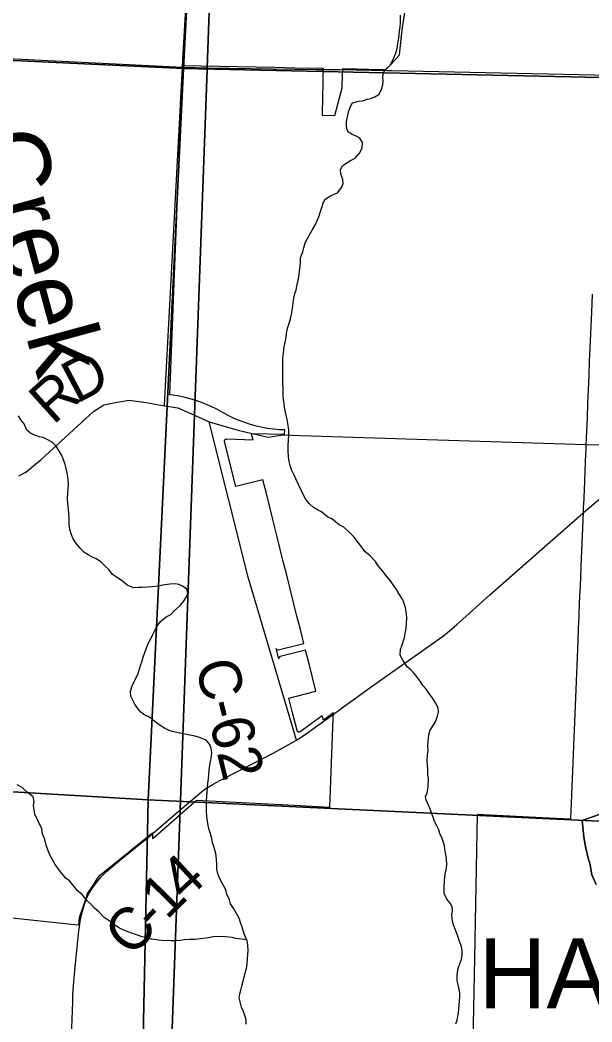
# Model space of a CAD drawing. Extents: x -7.5 to 26.5, y 3.5 to 25.5.
# Drawn here: x -2.42 to -1.65, y 21.822 to 23.173 of the extents above; entities that cross this region are included whole.
import ezdxf

# ---------------------------------------------------------------- set-up
doc = ezdxf.new("R2010")
doc.units = 0
for name, color, linetype in [('GM_X_Corporation', 7, 'Continuous'), ('GM_X_Corporation_Text', 7, 'Continuous'), ('GM_X_County_Road', 7, 'Continuous'), ('GM_X_County_Road_Text', 7, 'Continuous'), ('GM_X_Minor_River', 7, 'Continuous'), ('GM_X_Minor_River_Text', 7, 'Continuous')]:
    doc.layers.add(name, color=color, linetype=linetype)

msp = doc.modelspace()

# ---------------------------------------------------------------- linework, layer by layer
at = {"layer": 'GM_X_Corporation'}
for points in [[(-3.3166, 19.1895), (-2.696, 19.1768), (-2.693, 19.1768), (-2.3401, 19.1651), (-2.3128, 19.1642), (-2.2728, 20.2496), (-2.265, 20.4395), (-2.2643, 20.4572), (-2.2393, 21.1622), (-2.2218, 21.6412), (-2.2048, 22.1084), (-2.1854, 22.6407), (-2.1684, 23.1064), (-2.1683, 23.1094), (-2.1213, 24.4), (-5.1194, 24.4)], [(-2.1213, 24.4), (-2.1683, 23.1094), (-2.1684, 23.1064), (-2.1854, 22.6407), (-2.2048, 22.1084), (-2.2218, 21.6412), (-2.2393, 21.1622), (-1.7013, 21.1435), (-0.6673, 21.1123), (-0.2751, 21.1005), (-0.1918, 21.0972), (-0.1864, 21.0971), (-0.1806, 21.0967), (-0.0857, 21.093), (-0.0438, 21.0913), (0.0729, 21.0875), (0.2211, 21.0828)], [(-2.4486, 21.964), (-2.3846, 21.9575), (-2.3469, 21.9535), (-2.3413, 21.9531), (-2.3403, 21.9627), (-2.3345, 21.9798), (-2.3315, 21.9885), (-2.3293, 21.9951), (-2.3251, 22.0015), (-2.3137, 22.0189), (-2.2417, 22.0771), (-2.2419, 22.0696), (-2.238, 22.0727), (-2.1826, 22.1209), (-2.0595, 22.1147), (-2.0029, 22.1118), (-1.9982, 22.2314), (-1.9979, 22.2387), (-2.0116, 22.2289), (-2.0131, 22.2348), (-2.0427, 22.2134), (-2.0431, 22.2132), (-2.0435, 22.213), (-2.044, 22.2129), (-2.0444, 22.2129), (-2.0449, 22.213), (-2.0453, 22.2131), (-2.0458, 22.2133), (-2.0461, 22.2135), (-2.0465, 22.2138), (-2.0468, 22.2142), (-2.047, 22.2146), (-2.0471, 22.215), (-2.0536, 22.2405), (-2.0583, 22.2589), (-2.0215, 22.2682), (-2.0262, 22.2865), (-2.0309, 22.3049), (-2.0356, 22.3234), (-2.07, 22.3147), (-2.0704, 22.3146), (-2.0707, 22.3144), (-2.071, 22.3142), (-2.0712, 22.3139), (-2.0715, 22.3136), (-2.0716, 22.3133), (-2.0717, 22.3129), (-2.0718, 22.3125), (-2.0718, 22.3122), (-2.0717, 22.3118), (-2.0752, 22.3256), (-2.0751, 22.3252), (-2.0749, 22.3249), (-2.0747, 22.3246), (-2.0744, 22.3243), (-2.0741, 22.3241), (-2.0738, 22.324), (-2.0734, 22.3239), (-2.0731, 22.3238), (-2.0727, 22.3238), (-2.0723, 22.3239), (-2.0379, 22.3326), (-2.0426, 22.3511), (-2.0473, 22.3695), (-2.0519, 22.3878), (-2.0564, 22.4062), (-2.061, 22.4246), (-2.0656, 22.443), (-2.0701, 22.4614), (-2.0747, 22.4798), (-2.0793, 22.4981), (-2.0838, 22.5165), (-2.0884, 22.5349), (-2.093, 22.5533), (-2.1297, 22.5442), (-2.1448, 22.6048), (-2.1448, 22.6051), (-2.1448, 22.6055), (-2.1448, 22.606), (-2.1447, 22.6064), (-2.1445, 22.6068), (-2.1442, 22.6072), (-2.1439, 22.6075), (-2.1436, 22.6078), (-2.1432, 22.608), (-2.1428, 22.6082), (-2.1424, 22.6083), (-2.1419, 22.6083), (-2.1064, 22.6073), (-2.1066, 22.6083), (-2.1083, 22.6149), (-2.1085, 22.6159), (-2.0638, 22.6148), (-2.0636, 22.6201), (-2.0636, 22.6204), (-2.0712, 22.6207), (-2.0788, 22.6214), (-2.0863, 22.6224), (-2.0938, 22.6238), (-2.1017, 22.6256), (-2.1096, 22.6278), (-2.1174, 22.6303), (-2.1251, 22.6332), (-2.1326, 22.6365), (-2.14, 22.6401), (-2.1471, 22.6441), (-2.155, 22.6484), (-2.163, 22.6523), (-2.1712, 22.6558), (-2.1795, 22.659), (-2.188, 22.6617), (-2.1966, 22.664), (-2.2054, 22.666), (-2.2142, 22.6674), (-2.2144, 22.6675), (-2.2183, 22.668), (-2.2121, 22.8305), (-2.2069, 22.9655), (-2.2042, 23.0366), (-2.2034, 23.0548), (-2.2012, 23.1121), (-2.0776, 23.1096), (-2.049, 23.109), (-2.0119, 23.1083), (-2.012, 23.1026), (-2.0121, 23.1007), (-2.0122, 23.0926), (-2.0124, 23.0828), (-2.0126, 23.0743), (-2.0128, 23.0637), (-2.013, 23.0531), (-2.0132, 23.0451), (-1.9962, 23.0447), (-1.9861, 23.0818), (-1.9856, 23.1002), (-1.9853, 23.1078), (-1.9671, 23.1074), (-1.934, 23.1067), (-1.9274, 23.1066), (-1.9204, 23.114), (-1.9089, 23.1263), (-1.9054, 23.1601), (-1.8992, 23.201)], [(-1.6494, 22.8036), (-1.6499, 22.7904), (-1.6508, 22.7695), (-1.6516, 22.7506), (-1.6523, 22.7317), (-1.6531, 22.7127), (-1.6539, 22.6938), (-1.6547, 22.6749), (-1.6555, 22.656), (-1.6562, 22.637), (-1.657, 22.6181), (-1.6574, 22.6094), (-1.6574, 22.6082), (-1.6577, 22.6019), (-1.6579, 22.5966), (-1.658, 22.5943), (-1.6583, 22.5867), (-1.6587, 22.578), (-1.6598, 22.551), (-1.6602, 22.5399), (-1.6611, 22.5196), (-1.6612, 22.5166), (-1.6615, 22.5092), (-1.6615, 22.5077), (-1.6618, 22.5009), (-1.6619, 22.4987), (-1.664, 22.4471), (-1.6645, 22.4368), (-1.6651, 22.4218), (-1.6656, 22.4095), (-1.6661, 22.3972), (-1.6666, 22.3849), (-1.6671, 22.3726), (-1.6673, 22.3688), (-1.6679, 22.3535), (-1.6686, 22.3353), (-1.6695, 22.314), (-1.6785, 22.0956), (-1.7075, 22.097), (-1.8042, 22.1019), (-1.8079, 21.9086), (-1.8101, 21.7954)]]:
    msp.add_lwpolyline(points, dxfattribs=at)
for points in [[(-3.1693, 24.148), (-2.147, 24.1207), (-2.1999, 23.1078), (-3.2023, 23.155), (-3.2132, 23.1565)], [(-2.147, 24.1207), (-0.8988, 24.09), (-0.9286, 23.0807), (-2.1999, 23.1078)], [(-3.2023, 23.155), (-2.1999, 23.1078), (-2.2479, 22.1217), (-3.2367, 22.18)], [(-2.1999, 23.1078), (-0.9286, 23.0807), (-0.9291, 23.0451), (-0.9461, 22.0601), (-2.2479, 22.1217)], [(-3.2367, 22.18), (-2.2479, 22.1217), (-2.268, 21.1618), (-3.2602, 21.1789)], [(-2.2479, 22.1217), (-0.9461, 22.0601), (-0.9782, 21.2998), (-1.0267, 21.301), (-1.0307, 21.1237), (-1.2798, 21.1309), (-2.268, 21.1618)]]:
    msp.add_lwpolyline(points, close=True, dxfattribs=at)
at = {"layer": 'GM_X_County_Road'}
msp.add_line((-2.2258, 22.6528), (-2.2253, 22.663), dxfattribs=at)
for points in [[(-2.2008, 23.1201), (-2.1874, 23.3495), (-2.1808, 23.4761), (-2.1743, 23.6146), (-2.1737, 23.6247)], [(-2.6198, 23.1291), (-2.6056, 23.1283), (-2.5689, 23.1263), (-2.4645, 23.1228), (-2.2014, 23.11)], [(-2.2253, 22.663), (-2.2249, 22.6711), (-2.2014, 23.11), (-2.2008, 23.1201)], [(-2.2014, 23.11), (-2.1681, 23.1089), (-2.0209, 23.1066), (-2.0097, 23.1066)], [(-2.0097, 23.1066), (-1.9943, 23.1066), (-1.9893, 23.1065)], [(-1.9893, 23.1065), (-1.9258, 23.1052), (-1.9187, 23.1051)], [(-1.9187, 23.1051), (-1.6459, 23.0994), (-1.6361, 23.0992)], [(-1.6568, 22.6007), (-1.6367, 22.6004), (-1.5995, 22.5991), (-1.5848, 22.5989), (-1.5737, 22.6001), (-1.5662, 22.6016), (-1.5536, 22.6067), (-1.5321, 22.6175), (-1.5067, 22.63), (-1.4479, 22.6575), (-1.3991, 22.6922), (-1.3695, 22.7151), (-1.1787, 22.8635), (-0.9469, 23.0417)], [(-2.4221, 22.5586), (-2.4125, 22.5636), (-2.3918, 22.5808), (-2.3213, 22.6453), (-2.3074, 22.6544), (-2.2921, 22.6577), (-2.2734, 22.6605), (-2.2503, 22.6574), (-2.2258, 22.6528)], [(-2.2258, 22.6528), (-2.2077, 22.6503), (-2.1852, 22.6402), (-2.1653, 22.6313), (-2.1251, 22.6197)], [(-2.0477, 22.2022), (-2.1131, 22.4221), (-2.1653, 22.6313)], [(-2.1251, 22.6197), (-2.121, 22.6186), (-2.086, 22.6106), (-2.0745, 22.6125)], [(-2.0745, 22.6125), (-2.0661, 22.6139), (-2.0426, 22.6128), (-1.6579, 22.6007), (-1.6568, 22.6007)], [(-1.6586, 22.5107), (-1.6175, 22.5459), (-1.5895, 22.5709), (-1.5639, 22.5954), (-1.5536, 22.6067)], [(-1.9899, 22.2428), (-1.9875, 22.2446), (-1.9439, 22.276), (-1.8695, 22.329), (-1.848, 22.3442), (-1.8316, 22.3581), (-1.8149, 22.3729), (-1.7874, 22.3982), (-1.6617, 22.5081), (-1.6586, 22.5107)], [(-2.2023, 22.1099), (-2.1823, 22.1271), (-2.1755, 22.1326), (-2.1698, 22.1367), (-2.1647, 22.1398), (-2.1601, 22.1425), (-2.15, 22.148), (-2.1264, 22.1602), (-2.0782, 22.1849), (-2.0477, 22.2022), (-2.0359, 22.2099), (-2.0216, 22.2201), (-2.006, 22.2312)], [(-2.006, 22.2312), (-2.0044, 22.2324), (-1.9899, 22.2428)], [(-2.3396, 21.9573), (-2.3377, 21.9665), (-2.3351, 21.9763), (-2.3331, 21.9821), (-2.3298, 21.9901), (-2.3272, 21.9956), (-2.3225, 22.0031), (-2.3171, 22.0107), (-2.3114, 22.0174), (-2.3038, 22.0249), (-2.2896, 22.0369), (-2.2675, 22.0549), (-2.2474, 22.0711), (-2.2046, 22.1079), (-2.2023, 22.1099)], [(-2.3675, 21.6474), (-2.3584, 21.7252), (-2.3531, 21.7795), (-2.3506, 21.814), (-2.3494, 21.849), (-2.3492, 21.857), (-2.3487, 21.8659), (-2.3479, 21.8755), (-2.3468, 21.8862), (-2.3416, 21.9409), (-2.3405, 21.9508), (-2.3396, 21.9573)]]:
    msp.add_lwpolyline(points, dxfattribs=at)
at = {"layer": 'GM_X_Minor_River'}
for points in [[(-1.9788, 23.0226), (-1.9805, 23.0287), (-1.9803, 23.0363), (-1.979, 23.0427), (-1.9772, 23.051), (-1.9751, 23.0566), (-1.9723, 23.0615), (-1.9643, 23.0639), (-1.9589, 23.0645), (-1.9524, 23.0666), (-1.9474, 23.0675), (-1.942, 23.0697), (-1.937, 23.0729), (-1.9337, 23.0789), (-1.9316, 23.086), (-1.9311, 23.091), (-1.9313, 23.0963), (-1.9307, 23.102), (-1.9276, 23.1068), (-1.9217, 23.1123), (-1.9189, 23.1175), (-1.9164, 23.1224), (-1.9139, 23.1288), (-1.9122, 23.1355), (-1.9108, 23.1442), (-1.9099, 23.1491), (-1.9089, 23.1586), (-1.9079, 23.1639), (-1.9074, 23.1699), (-1.9075, 23.1798)], [(-1.9166, 22.4104), (-1.9213, 22.417), (-1.9268, 22.4236), (-1.9316, 22.4302), (-1.9375, 22.4372), (-1.9415, 22.443), (-1.9485, 22.4508), (-1.9555, 22.4567), (-1.9599, 22.4622), (-1.9647, 22.4688), (-1.9698, 22.4754), (-1.9757, 22.4817), (-1.9839, 22.4895), (-1.9902, 22.4924), (-2.0003, 22.5006), (-2.0059, 22.5031), (-2.0141, 22.5098), (-2.0193, 22.5126), (-2.0249, 22.5158), (-2.0301, 22.5209), (-2.0353, 22.5268), (-2.0385, 22.5326), (-2.0417, 22.5391), (-2.0453, 22.5468), (-2.0485, 22.5545), (-2.051, 22.5595), (-2.0546, 22.5668), (-2.0563, 22.5726), (-2.0577, 22.5779), (-2.0587, 22.584), (-2.0588, 22.5924), (-2.059, 22.5989), (-2.0584, 22.6068), (-2.0581, 22.6144), (-2.0583, 22.6201), (-2.0589, 22.6266), (-2.0602, 22.6346), (-2.0625, 22.6445), (-2.0639, 22.6506), (-2.0645, 22.6563), (-2.0651, 22.6613), (-2.0657, 22.6678), (-2.0658, 22.6761), (-2.0663, 22.6845), (-2.0664, 22.694), (-2.0662, 22.6989), (-2.066, 22.7072), (-2.0662, 22.7122), (-2.0661, 22.7175), (-2.0655, 22.7247), (-2.0645, 22.7326), (-2.0631, 22.7383), (-2.0618, 22.7454), (-2.0612, 22.7507), (-2.0599, 22.7579), (-2.0578, 22.7639), (-2.0557, 22.7703), (-2.0544, 22.7767), (-2.0538, 22.782), (-2.0529, 22.7869), (-2.0524, 22.7922), (-2.0515, 22.7979), (-2.0501, 22.8043), (-2.0484, 22.8092), (-2.0467, 22.8171), (-2.0453, 22.8239), (-2.0434, 22.8379), (-2.0424, 22.8458), (-2.0422, 22.853), (-2.0393, 22.8609), (-2.038, 22.8662), (-2.0359, 22.8729), (-2.033, 22.8785), (-2.0302, 22.8838), (-2.0266, 22.8901), (-2.0222, 22.8976), (-2.0197, 22.9028), (-2.0177, 22.908), (-2.0148, 22.9163), (-2.0131, 22.9219), (-2.0118, 22.9268), (-2.0086, 22.9317), (-2.0027, 22.936), (-1.9977, 22.9382), (-1.9923, 22.9403), (-1.9868, 22.9481), (-1.9847, 22.9529), (-1.9853, 22.9583), (-1.9878, 22.9656), (-1.9883, 22.9717), (-1.9859, 22.9765), (-1.9808, 22.9805), (-1.975, 22.9838), (-1.9689, 22.987), (-1.9629, 22.9936), (-1.9593, 23.0004), (-1.9587, 23.0083), (-1.9623, 23.0141), (-1.9672, 23.0169), (-1.9728, 23.019), (-1.9788, 23.0226)], [(-2.2001, 22.3892), (-2.1961, 22.3955), (-2.1944, 22.4004), (-2.1958, 22.4057), (-2.2013, 22.4097), (-2.2062, 22.4121), (-2.2115, 22.4131), (-2.2184, 22.4125), (-2.228, 22.4109), (-2.2341, 22.4096), (-2.2417, 22.4087), (-2.249, 22.4085), (-2.2562, 22.408), (-2.2615, 22.4078), (-2.2676, 22.4076), (-2.2759, 22.4113), (-2.2826, 22.4168), (-2.2904, 22.422), (-2.2957, 22.4255), (-2.3008, 22.4321), (-2.3056, 22.4369), (-2.3115, 22.4427), (-2.3179, 22.4467), (-2.3235, 22.4492), (-2.3284, 22.452), (-2.3343, 22.4556), (-2.3395, 22.4611), (-2.3443, 22.4669), (-2.3486, 22.4735), (-2.3511, 22.4789), (-2.3532, 22.4862), (-2.3541, 22.4934), (-2.3543, 22.4995), (-2.3548, 22.5082), (-2.355, 22.5135), (-2.356, 22.5212), (-2.3565, 22.528), (-2.3559, 22.5356), (-2.3554, 22.5409), (-2.3552, 22.5469), (-2.3554, 22.553), (-2.3563, 22.5603), (-2.3597, 22.574), (-2.3625, 22.5817), (-2.3646, 22.5867), (-2.3686, 22.5937), (-2.3723, 22.5991), (-2.3771, 22.6042), (-2.3838, 22.6078), (-2.3894, 22.6102), (-2.3944, 22.6112), (-2.4011, 22.6136), (-2.4064, 22.6161), (-2.4112, 22.62), (-2.4148, 22.6285), (-2.4192, 22.6343), (-2.4224, 22.6394)], [(-1.8328, 21.8195), (-1.8311, 21.8243), (-1.8293, 21.8338), (-1.828, 21.8504), (-1.8275, 21.8557), (-1.8277, 21.8611), (-1.8287, 21.866), (-1.83, 21.8718), (-1.831, 21.8775), (-1.8312, 21.8832), (-1.8306, 21.8892), (-1.8297, 21.8941), (-1.8277, 21.9002), (-1.8252, 21.9065), (-1.8246, 21.9118), (-1.8245, 21.9179), (-1.8254, 21.9236), (-1.8279, 21.9305), (-1.83, 21.9363), (-1.8332, 21.9447), (-1.836, 21.9528), (-1.8373, 21.9581), (-1.8386, 21.9658), (-1.8377, 21.9722), (-1.8379, 21.9771), (-1.8408, 21.9822), (-1.8452, 21.9876), (-1.8488, 21.9953), (-1.8489, 22.0037), (-1.8482, 22.0128), (-1.8472, 22.0218), (-1.8458, 22.0294), (-1.8453, 22.0343), (-1.8458, 22.0419), (-1.8464, 22.0476), (-1.8477, 22.0549), (-1.8483, 22.0598), (-1.8515, 22.0694), (-1.8547, 22.0763), (-1.8561, 22.0813), (-1.8586, 22.0867), (-1.8618, 22.0925), (-1.8636, 22.0983), (-1.8657, 22.104), (-1.8674, 22.1094), (-1.8731, 22.1209), (-1.8738, 22.1259), (-1.8717, 22.1308), (-1.8703, 22.1391), (-1.87, 22.1504), (-1.8706, 22.1554), (-1.8707, 22.163), (-1.8714, 22.168), (-1.8715, 22.1744), (-1.8713, 22.1816), (-1.8704, 22.188), (-1.8706, 22.1945), (-1.8698, 22.2055), (-1.8689, 22.2108), (-1.8676, 22.2157), (-1.8636, 22.2216), (-1.8604, 22.2268), (-1.8576, 22.2343), (-1.8562, 22.2404), (-1.8568, 22.2457), (-1.8604, 22.2523), (-1.8648, 22.2596), (-1.8696, 22.2654), (-1.8728, 22.2709), (-1.8776, 22.2759), (-1.8813, 22.2814), (-1.8853, 22.2868), (-1.8893, 22.2919), (-1.8937, 22.2969), (-1.8986, 22.3009), (-1.9051, 22.3109), (-1.908, 22.3167), (-1.9074, 22.3243), (-1.9053, 22.3307), (-1.9023, 22.3405), (-1.9014, 22.3457), (-1.9, 22.3525), (-1.8994, 22.3605), (-1.8989, 22.3662), (-1.8994, 22.3726), (-1.9007, 22.381), (-1.9025, 22.3864), (-1.9046, 22.3914), (-1.9097, 22.3999), (-1.9129, 22.4053), (-1.9166, 22.4104)], [(-2.1156, 21.8191), (-2.1158, 21.8248), (-2.1175, 21.8306), (-2.1196, 21.8371), (-2.1218, 21.8421), (-2.1238, 21.849), (-2.1252, 21.8547), (-2.1243, 21.86), (-2.123, 21.8649), (-2.1213, 21.8702), (-2.1196, 21.8769), (-2.1183, 21.8826), (-2.1148, 21.8962), (-2.1143, 21.9011), (-2.1137, 21.9071), (-2.1132, 21.9128), (-2.113, 21.9177), (-2.1135, 21.9265), (-2.1145, 21.9314), (-2.1173, 21.9387), (-2.1191, 21.9441), (-2.1208, 21.9499), (-2.1226, 21.9548), (-2.125, 21.9621), (-2.1286, 21.9683), (-2.1322, 21.9745), (-2.1366, 21.9815), (-2.1383, 21.9865), (-2.1415, 21.9945), (-2.1436, 22.001), (-2.1479, 22.0091), (-2.1505, 22.0142), (-2.1533, 22.0203), (-2.155, 22.028), (-2.1552, 22.0337), (-2.1557, 22.0417), (-2.1566, 22.0493), (-2.1594, 22.0585), (-2.1608, 22.0634), (-2.1621, 22.0696), (-2.1638, 22.0757), (-2.1656, 22.081), (-2.1669, 22.0868), (-2.1679, 22.0929), (-2.1685, 22.099), (-2.169, 22.1066), (-2.1691, 22.1149), (-2.169, 22.1202), (-2.1671, 22.1441), (-2.1665, 22.1498), (-2.166, 22.1562), (-2.1649, 22.1657), (-2.1636, 22.1732), (-2.1622, 22.1804), (-2.162, 22.1853), (-2.1626, 22.1906), (-2.1648, 22.196), (-2.1695, 22.2019), (-2.1748, 22.2043), (-2.1801, 22.206), (-2.1861, 22.2081), (-2.1914, 22.209), (-2.1978, 22.2103), (-2.2031, 22.2109), (-2.2092, 22.2122), (-2.2152, 22.2139), (-2.2201, 22.2156), (-2.2258, 22.218), (-2.2314, 22.222), (-2.2366, 22.2256), (-2.247, 22.2335), (-2.2523, 22.2356), (-2.2575, 22.2399), (-2.2619, 22.2453), (-2.2655, 22.2508), (-2.2684, 22.2558), (-2.2709, 22.2616), (-2.2715, 22.2677), (-2.2698, 22.2741), (-2.2665, 22.2812), (-2.2641, 22.286), (-2.2612, 22.292), (-2.2579, 22.3029), (-2.2558, 22.3089), (-2.2545, 22.3138), (-2.2524, 22.3202), (-2.2503, 22.3254), (-2.2478, 22.3322), (-2.2442, 22.3389), (-2.2418, 22.3438), (-2.2385, 22.3509), (-2.2349, 22.3572), (-2.2313, 22.3621), (-2.2235, 22.3686), (-2.2173, 22.3715), (-2.2122, 22.377), (-2.2044, 22.3836), (-2.2001, 22.3892)], [(-2.1149, 21.9325), (-2.1296, 21.9346), (-2.1345, 21.9359), (-2.1433, 21.9369), (-2.1494, 21.9371), (-2.16, 21.9367), (-2.1669, 21.9353), (-2.1738, 21.9344), (-2.1845, 21.9332), (-2.1925, 21.9331), (-2.199, 21.9325), (-2.2047, 21.932), (-2.2108, 21.9314), (-2.2177, 21.9312), (-2.2298, 21.9316), (-2.237, 21.9326), (-2.2427, 21.9335), (-2.2476, 21.9348), (-2.256, 21.9366), (-2.262, 21.9391), (-2.2725, 21.9424), (-2.2785, 21.9449), (-2.2864, 21.9485), (-2.2939, 21.9533), (-2.2991, 21.9573), (-2.3069, 21.9628), (-2.3143, 21.9703), (-2.3199, 21.9754), (-2.3247, 21.9805), (-2.3299, 21.9852), (-2.3365, 21.9937), (-2.3428, 21.9989), (-2.3475, 22.0047), (-2.3538, 22.0121), (-2.3586, 22.0161), (-2.3641, 22.0223), (-2.3685, 22.0281), (-2.3733, 22.0344), (-2.3787, 22.0448), (-2.3816, 22.0506), (-2.3851, 22.0602), (-2.3871, 22.0682), (-2.39, 22.0755), (-2.3909, 22.0823), (-2.3959, 22.0927), (-2.4006, 22.102), (-2.4015, 22.1081), (-2.4021, 22.1134), (-2.4012, 22.1195), (-2.4029, 22.1256), (-2.4122, 22.1327), (-2.4174, 22.1382), (-2.4241, 22.1418)], [(-1.6398, 22.1019), (-1.6626, 22.0935), (-1.6606, 22.0717), (-1.6591, 22.0629), (-1.6576, 22.0562), (-1.654, 22.0413), (-1.6525, 22.0361), (-1.6496, 22.0203), (-1.6438, 22.0074)], [(-1.6438, 22.0074), (-1.6496, 22.0203), (-1.6525, 22.0361), (-1.654, 22.0413), (-1.6576, 22.0562), (-1.6591, 22.0629), (-1.6606, 22.0717), (-1.6626, 22.0935), (-1.6398, 22.1019)]]:
    msp.add_lwpolyline(points, dxfattribs=at)

# ---------------------------------------------------------------- texts
at = {"layer": 'GM_X_Corporation_Text'}
msp.add_text('HARRISON', height=0.0947, rotation=0, dxfattribs=at).set_placement((-1.8024, 21.8402))
at = {"layer": 'GM_X_County_Road_Text'}
for s, height, rotation, p in [('D', 0.0568, 27.8796, (-2.344, 22.6554)), ('R', 0.0568, 42.0212, (-2.3757, 22.6262)), ('C-62', 0.05682, 283.8698, (-2.1847, 22.3045)), ('4', 0.0568, 43.0071, (-2.1983, 21.983)), ('1', 0.0568, 45.3813, (-2.2224, 21.9585)), ('C', 0.0568, 46.6374, (-2.2704, 21.9079)), ('-', 0.0568, 46.3365, (-2.2384, 21.9418))]:
    msp.add_text(s, height=height, rotation=rotation, dxfattribs=at).set_placement(p)
at = {"layer": 'GM_X_Minor_River_Text'}
msp.add_text('Creek', height=0.0947, rotation=285.2738, dxfattribs=at).set_placement((-2.4852, 23.0129))

doc.saveas('drawing.dxf')
